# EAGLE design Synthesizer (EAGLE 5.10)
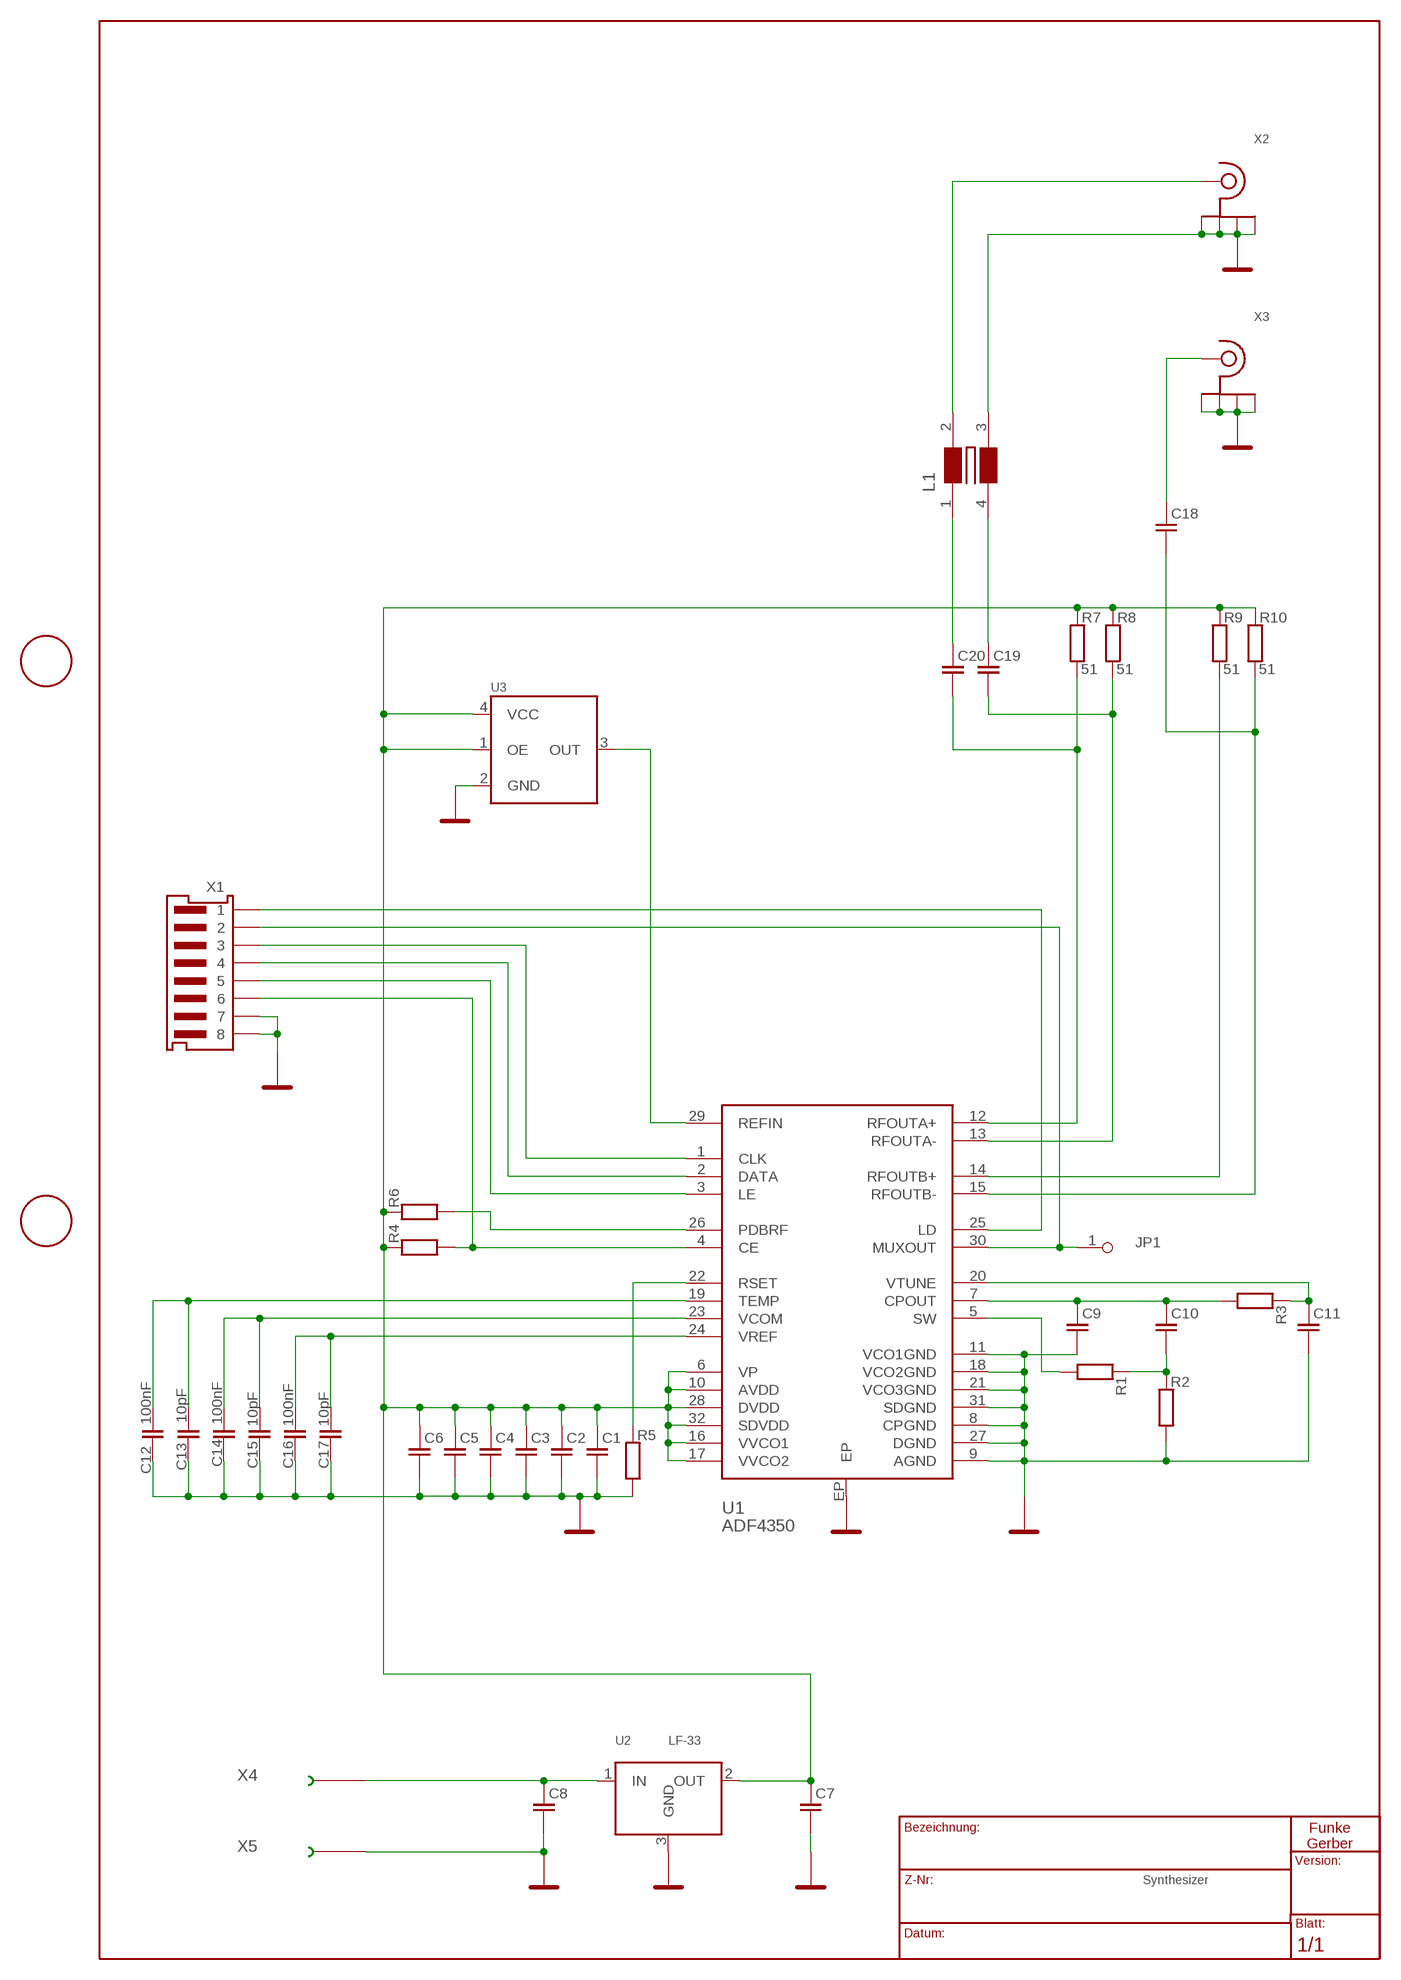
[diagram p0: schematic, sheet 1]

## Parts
C1  SMD-0603  [SOT-0603]
C2  SMD-0603  [SOT-0603]
C3  SMD-0603  [SOT-0603]
C4  SMD-0603  [SOT-0603]
C5  SMD-0603  [SOT-0603]
C6  SMD-0603  [SOT-0603]
C7  SMD-1210  [SOT-1210]
C8  SMD-1210  [SOT-1210]
C9  SMD-0603  [SOT-0603]
C10  SMD-0603  [SOT-0603]
C11  SMD-0603  [SOT-0603]
C12  100nF  SMD-0603  [SOT-0603]
C13  10pF  SMD-0603  [SOT-0603]
C14  100nF  SMD-0603  [SOT-0603]
C15  10pF  SMD-0603  [SOT-0603]
C16  100nF  SMD-0603  [SOT-0603]
C17  10pF  SMD-0603  [SOT-0603]
C18  SMD-0603  [SOT-0603]
C19  SMD-0603  [SOT-0603]
C20  SMD-0603  [SOT-0603]
JP1  PINHD-1X1  [1X01]
L1  WE-DD_M/S  [WE-DD_M/S]
R1  SMD-0603  [SMD-0603]
R2  SMD-0603  [SMD-0603]
R3  SMD-0603  [SMD-0603]
R4  SMD-0603  [SMD-0603]
R5  SMD-0603  [SMD-0603]
R6  SMD-0603  [SMD-0603]
R7  51  SMD-0603  [SMD-0603]
R8  51  SMD-0603  [SMD-0603]
R9  51  SMD-0603  [SMD-0603]
R10  51  SMD-0603  [SMD-0603]
U1  ADF4350  ADF4350CP-32-2  [CP32-2]
U2  LF-33  LF-XXX  [DPAK]
U3  SG-710  [SG710]
X1  LUMBG8  [LUMBG8]
X2  SMA-EDGE  [SMA-EDGE]
X3  SMA-EDGE  [SMA-EDGE]
X4  LÖTÖSEQ  [LÖTÖSEQ]
X5  LÖTÖSEQ  [LÖTÖSEQ]

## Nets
+3.3V: C1.2 C2.2 C3.2 C4.2 C5.2 C6.2 C7.2 R4.2 R6.2 R7.2 R8.2 R9.2 R10.2 U1.6(VP) U1.10(AVDD) U1.16(VVCO1) U1.17(VVCO2) U1.28(DVDD) U1.32(SDVDD) U2.2(OUT) U3.1(OE) U3.4(VCC)
+5V: C8.2 U2.1(IN) X4.1
A+: C20.1 R7.1 U1.12(RFOUTA+)
A-: C19.1 R8.1 U1.13(RFOUTA-)
B+: R9.1 U1.14(RFOUTB+)
B-: C18.1 R10.1 U1.15(RFOUTB-)
CH_PU: C9.2 C10.2 R3.1 U1.7(CPOUT)
GND: C1.1 C2.1 C3.1 C4.1 C5.1 C6.1 C7.1 C8.1 C9.1 C11.1 C12.2 C13.2 C14.1 C15.1 C16.1 C17.1 L1.3 R2.1 R5.1 U1.8(CPGND) U1.9(AGND) U1.11(VCO1GND) U1.18(VCO2GND) U1.21(VCO3GND) U1.27(DGND) U1.31(SDGND) U1.EP U2.3(GND) U3.2(GND) X1.7 X1.8 X2.GND@1(GND) X2.GND@2(GND) X2.GND@3(GND) X2.GND@4(GND) X3.GND@1(GND) X3.GND@2(GND) X3.GND@3(GND) X3.GND@4(GND) X5.1
N$3: C10.1 R1.2 R2.2
N$4: R1.1 U1.5(SW)
N$5: R4.1 U1.4(CE) X1.6
N$6: R5.2 U1.22(RSET)
N$7: C12.1 C13.1 U1.19(TEMP)
N$8: C14.2 C15.2 U1.23(VCOM)
N$9: C16.2 C17.2 U1.24(VREF)
N$10: U1.3(LE) X1.5
N$11: U1.2(DATA) X1.4
N$12: U1.1(CLK) X1.3
N$13: U1.25(LD) X1.1
N$14: JP1.1 U1.30(MUXOUT) X1.2
N$15: R6.1 U1.26(PDBRF)
N$16: C18.2 X3.A
N$17: U1.29(REFIN) U3.3(OUT)
N$18: C19.2 L1.4
N$19: C20.2 L1.1
N$20: L1.2 X2.A
TUNE: C11.2 R3.2 U1.20(VTUNE)

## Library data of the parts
C1-C6 C9-C20 = C_KERAM:SMD-0603
C7 C8 = C_KERAM:SMD-1210
JP1 = PINHD-Q:PINHD-1X1
L1 = WUERTH_6-6:WE-DD: SMD-Shielded Power Transformers (SEPIC) WE-DD - 1:1 transformer - Double inductor with two identical windings - Customer specific designs available upon request -- SEPIC-switching regulators -- Switching regulators with second, unregulated output voltag
R1-R10 = R:SMD-0603
U1 = ANALOG_D:ADF4350: 4.4 GHz Synthesizer mit integriertem VCO
U2 = SGS:LF-XXX
U3 = SEIK_EPS:SG-710
X1 = Z_CONNEC:LUMBG8
X2 X3 = HAMRAD:SMA-EDGE
X4 X5 = Z_CONNEC:LÖTÖSEQ

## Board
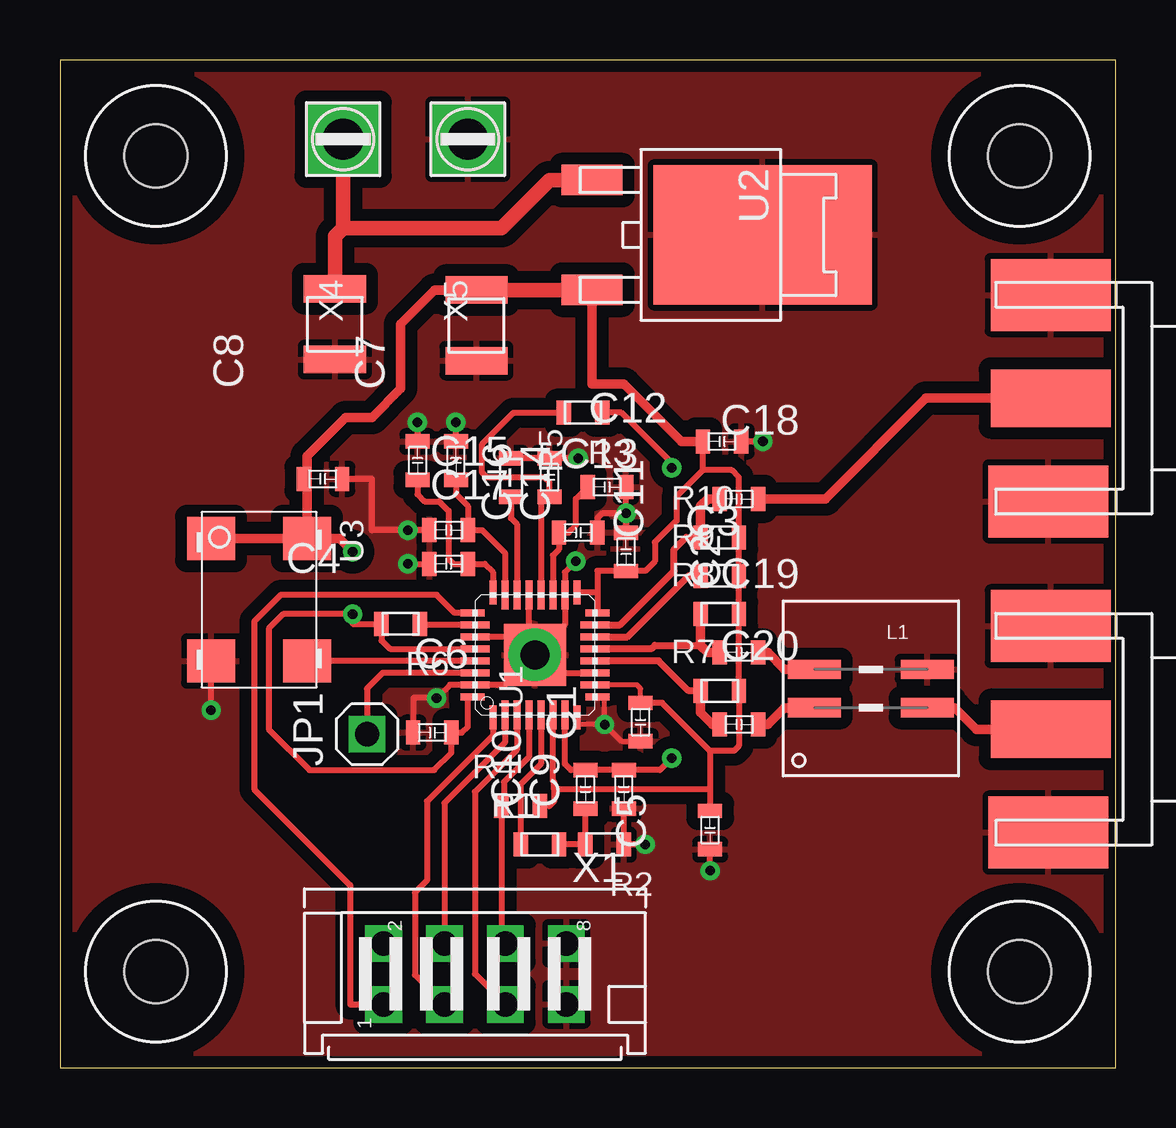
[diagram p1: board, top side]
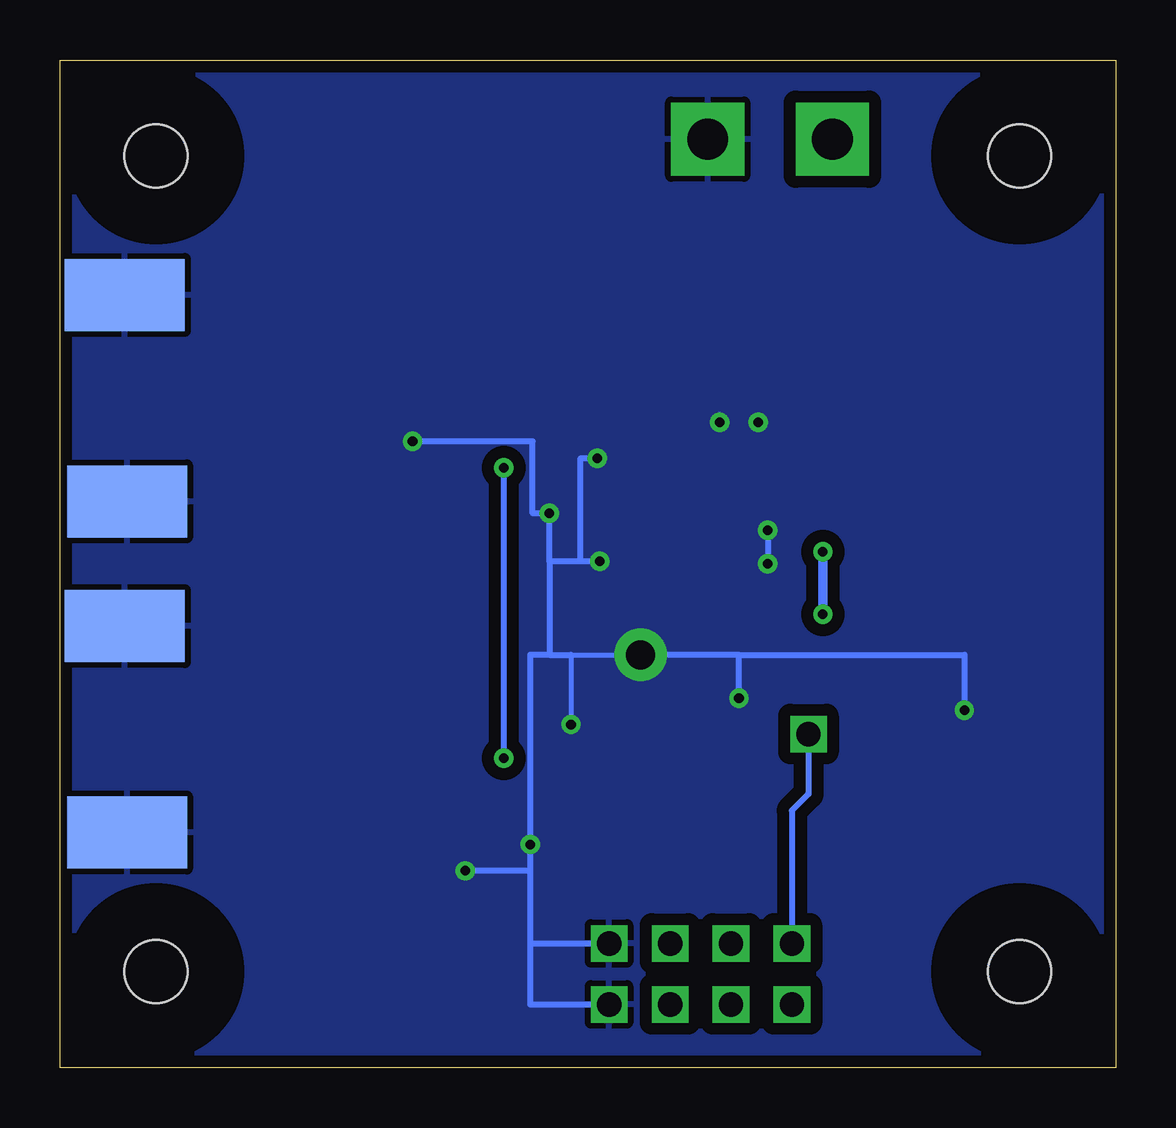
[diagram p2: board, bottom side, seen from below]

Size 44 x 42 mm. Coordinates in mm from the lower left corner, seen from the top.
Outline: 44,0 44,42 0,42 0,0 44,0
Copper layers (1*16): Top 0.035mm / dielectric 1.5mm / Bottom 0.035mm
Design rules "default": minimum track width 0.15mm, minimum drill 0.3mm, track to track 0.15mm, track to pad 0.15mm, pad to pad 0.15mm, via to via 0.15mm, smd to smd 0mil, copper to edge 0.15mm, drill to drill 0.15mm, minimum pad ring 0.15mm, minimum via ring 0.15mm, stop-mask expansion 4mil, vias tented up to drill 0mil, thermal gap 10mil

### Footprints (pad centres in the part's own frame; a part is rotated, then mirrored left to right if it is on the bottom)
SOT-0603 = smd 0.6 x 1: 1 -0.8,0; 2 0.8,0
SOT-1210 = smd 1.143 x 2.591: 1 -1.473,0; 2 1.473,0
1X01 = drill 1.016 pad 1.524 square: 1 0,0
WE-DD_M/S = smd 0.8 x 2.2: 1 0.8,-2.35; 2 0.8,2.35; 3 -0.8,2.35; 4 -0.8,-2.35
SMD-0603 = smd 0.6 x 1: 1 -0.8,0; 2 0.8,0
CP32-2 = smd 1 x 0.28: 1 -2.6,1.75; 8 -2.6,-1.75; 17 2.6,-1.75; 24 2.6,1.75 | smd 1.2 x 0.28: 2 -2.5,1.25; 3 -2.5,0.75; 4 -2.5,0.25; 5 -2.5,-0.25; 6 -2.5,-0.75; 7 -2.5,-1.25; 18 2.5,-1.25; 19 2.5,-0.75; 20 2.5,-0.25; 21 2.5,0.25; 22 2.5,0.75; 23 2.5,1.25 | smd 0.28 x 1: 9 -1.75,-2.6; 16 1.75,-2.6; 25 1.75,2.6; 32 -1.75,2.6 | smd 0.28 x 1.2: 10 -1.25,-2.5; 11 -0.75,-2.5; 12 -0.25,-2.5; 13 0.25,-2.5; 14 0.75,-2.5; 15 1.25,-2.5; 26 1.25,2.5; 27 0.75,2.5; 28 0.25,2.5; 29 -0.25,2.5; 30 -0.75,2.5; 31 -1.25,2.5 | smd 2.6 x 2.6: EP 0,0
DPAK = smd 1.27 x 2.54: 1 -2.286,-2.032; 2 2.286,-2.032 | smd 5.8 x 9.1: 3 0,5.08
SG710 = smd 1.8 x 2: 1 -2.55,-2; 2 2.55,-2; 3 2.55,2; 4 -2.55,2
DRIL-2,5 = hole 2.642: 0,0
LUMBG8 = drill 1.016 pad 1.422 square: 1 -1.27,3.81; 2 1.27,3.81; 3 -1.27,1.27; 4 1.27,1.27; 5 -1.27,-1.27; 6 1.27,-1.27; 7 -1.27,-3.81; 8 1.27,-3.81
SMA-EDGE = smd 5 x 2.4: A 0,0 | smd 5 x 3: GND@1 0,4.3; GND@2 -0.1,-4.3 | smd 5 x 3 bottom: GND@3 0,4.3; GND@4 -0.1,-4.3
LÖTÖSEQ = drill 1.702 pad 3.048 square: 1 0,0

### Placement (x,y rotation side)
C1  24.2,14.4 90 top
C2  23.6,21.5 270 top
C3  27.6,26.1 180 top
C4  10.96,24.54 180 top
C5  27.1,9.9 90 top
C6  15.52,13.96 0 top
C7  17.36,30.94 90 top
C8  11.46,30.99 90 top
C9  23.5,11.6 90 top
C10  21.9,11.6 90 top
C11  20.4,24.6 270 top
C12  22.8,24.2 0 top
C13  21.6,22.3 0 top
C14  16.5,25.3 270 top
C15  16.2,22.4 0 top
C16  14.9,25.3 270 top
C17  16.2,21 0 top
C18  28.3,23.7 0 top
C19  28.3,17.3 0 top
C20  28.3,14.3 0 top
JP1  12.8,13.9 90 top
L1  33.8,15.8 270 top
R1  20,9.3 0 top
R2  22.7,9.3 180 top
R3  21.8,27.3 180 top
R4  19.2,10.9 0 top
R5  18.8,24.6 270 top
R6  14.2,18.5 180 top
R7  27.5,15.7 0 top
R8  27.5,18.9 0 top
R9  27.5,20.5 0 top
R10  27.5,22.1 0 top
U1  19.8,17.2 90 top
U2  24.21,34.71 270 top
U3  8.3,19.5 270 top
U$11  [DRIL-2,5]  40,4 90 top
U$12  [DRIL-2,5]  40,38 90 top
U$13  [DRIL-2,5]  4,38 90 top
U$14  [DRIL-2,5]  4,4 90 top
X1  17.3,3.9 90 top
X2  41.3,14.1 0 top
X3  41.3,27.9 0 top
X4  11.8,38.7 90 top
X5  17,38.7 90 top

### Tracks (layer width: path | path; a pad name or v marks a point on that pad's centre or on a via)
+3.3V  (via drill 0.4 pad 0.8)
  Top 0.2: U1.10 24.05,15.95 24.2,15.8 C1.2
  Top 0.25: 27.1,13.2 28.1,13.2 28.3,13.4 R7.2 R8.2 R9.2 R10.2 28.3,24.6 28,24.9 26.8,24.9 | 27.1,13.2 25.1,15.2 C1.2 | 26.8,24.9 25.7,23.8 25.7,22.8 24.8,21.9 24.8,21.1 24.4,20.7 C2.2 22.4,20.7 22.4,19.8 | 22.4,19.8 U1.16 | 22.4,19.8 U1.17 | U1.6 20.55,11.95 20.6,11.9 20.6,11.6 | 27.1,13.2 27.1,11.6 | 26.8,24.9 C3.2 | U1.28 13.75,17.45 13.4,17.8 R6.2 12.2,18.5 v12.2,18.9 9.3,18.9 8.7,18.3 8.7,14.1 10.4,12.4 15.6,12.4 16.32,13.12 C6.2 16.76,13.96 17,14.2 17,15.45 U1.32 | 27.1,11.6 20.6,11.6 | 20.6,11.6 20.6,11.1 20.4,10.9 R4.2 | U2.2 21.87,32.41 | 27.1,11.6 C5.2
  Top 0.4: C3.2 25.9,26.1 23.5,28.5 22.18,28.5 U2.2 | U3.4 U3.1 | U3.4 11.65,22.05 v12.2,21.5 | 10.3,24.6 10.3,25.5 11.9,27.1 13,27.1 14.2,28.3 14.2,31 15.61,32.41 C7.2 | 10.3,24.6 U3.4 | C4.2 10.22,24.6 10.3,24.6
  Top 0.6: 21.87,32.41 C7.2
  Bottom 0.4: v12.2,21.5 v12.2,18.9
+5V
  Top 0.6: 11.8,35 18.4,35 20.4,37 U2.1 | 11.8,35 X4.1 | 11.8,35 11.46,34.66 C8.2
A+
  Top 0.3: U1.12 24.95,16.95 26.2,15.7 R7.1
  Top 0.4: C20.1 27.2,14.3 26.7,14.8 R7.1
A-
  Top 0.3: U1.13 24.65,17.45 24.8,17.6 26.7,17.6
  Top 0.4: R8.1 26.7,17.6 27,17.3 C19.1
B+
  Top 0.3: U1.14 23.65,17.95 26.2,20.5 R9.1
B-
  Top 0.3: U1.15 23.35,18.45 25.6,20.7 25.6,21.6 26.1,22.1 R10.1
  Top 0.4: R10.1 26.7,23.4 27,23.7 C18.1
CH_PU  (via drill 0.4 pad 0.8)
  Top 0.25: U1.7 21.05,12.65 21.3,12.4 C10.2 C9.2 25,12.4 v25.5,12.9 | v25.5,25 25.5,25.2 23.4,27.3 R3.1
  Bottom 0.25: v25.5,12.9 v25.5,25
GND  (via drill 0.4 pad 0.8, 1.2 pad 2.18)
  Top 0.2: C1.1 23.4,13.6 v22.7,14.3 | U1.8 21.55,14.3 v22.7,14.3 | U1.9 22.7,15.45 v22.7,14.3
  Top 0.25: v23.6,23.1 C2.1 | C13.2 22.4,22.9 22.6,23.1 v23.6,23.1 | U1.EP 21.05,18.45 U1.18 21.05,20.65 v21.5,21.1 | U1.11 20.55,16.45 U1.EP | U1.21 19.55,17.45 U1.EP | v21.6,25.4 C11.1 R5.1 | v23.6,23.1 C12.2 | U1.27 19.05,17.95 U1.EP | U1.EP 18.55,15.95 U1.31 16.25,15.95 v15.7,15.4 14.72,15.4 C6.1 | v24.4,9.3 R2.1 C9.1 | v29.3,26.1 C3.1 | v14.5,21 C17.1 | C15.1 v14.5,22.4 13,22.4 13,24.54 C4.1 | v14.9,26.9 C16.1 | C14.1 v16.5,26.9 | v6.3,14.9 U3.2 | v27.1,8.2 C5.1
  Bottom 0.2: v22.7,14.3 22.7,17.2 U1.EP
  Bottom 0.25: 23.6,21.1 23.6,17.2 | 23.6,21.1 v23.6,23.1 24.3,23.1 24.3,26.1 v29.3,26.1 | 23.6,17.2 22.7,17.2 | 22.3,21.1 23.6,21.1 | v21.5,21.1 22.3,21.1 | v21.6,25.4 22.3,25.4 22.3,21.1 | v15.7,15.4 15.7,17.2 | 15.7,17.2 19.7,17.2 | 23.6,17.2 24.4,17.2 v24.4,9.3 24.4,8.2 | 14.2,21 v14.5,21 v14.5,22.4 14.3,22.4 | 14.9,27.1 v14.9,26.9 | v16.5,26.9 16.5,27.2 | 24.4,5.17 X1.8 | 24.4,8.2 24.4,5.17 | X1.7 24.4,2.63 24.4,5.17 | v6.3,14.9 6.3,17.2 15.7,17.2 | 24.4,8.2 v27.1,8.2
  other vias: 19.8,17.2
  pour Bottom (isolate 0.5): 0.4,41.8 0.4,0.3 43.4,0.3 43.4,41.8
  pour Top (isolate 0.5): 0.4,41.8 0.4,0.3 43.4,0.3 43.4,41.8
N$3
  Top 0.25: R1.2 R2.2 C10.1
N$4
  Top 0.25: U1.5 20.05,12.65 19.2,11.8 R1.1
N$5
  Top 0.25: U1.4 19.55,12.95 18.5,11.9 18.5,11 R4.1 18.4,5.34 X1.6
N$6
  Top 0.25: U1.22 19.05,22.65 18.8,22.9 R5.2
N$7
  Top 0.25: U1.19 20.55,21.35 20.8,21.6 C13.1 21.2,22.3 21.5,22.6 21.5,23.7 C12.1
N$8
  Top 0.25: U1.23 18.55,21.45 17.6,22.4 C15.2 17,23.4 16.5,23.9 C14.2
N$9
  Top 0.25: U1.24 18.05,20.65 17.7,21 C17.2 16.4,21 16.2,21.2 16.2,23.2 15.8,23.6 15.2,23.6 14.9,23.9 C16.2
N$10
  Top 0.25: U1.3 19.05,13.25 17.3,11.5 17.3,3.9 X1.5
N$11
  Top 0.25: U1.2 18.55,13.55 16.03,11.03 X1.4
N$12
  Top 0.25: U1.1 18.05,13.85 15.3,11.1 15.3,7.8 14.8,7.3 14.8,3.86 X1.3
N$13
  Top 0.25: U1.25 16.45,18.95 15.7,19.7 9.2,19.7 8.1,18.6 8.1,11.6 12.1,7.6 12.1,2.63 X1.1
N$14
  Top 0.25: U1.30 13.45,16.45 12.8,15.8 JP1.1
  Bottom 0.25: X1.2 13.49,10.71 12.8,11.4 JP1.1
N$15
  Top 0.25: U1.26 15.05,18.45 R6.1
N$16
  Top 0.4: C18.2 31.9,23.7 36.1,27.9 X3.A
N$17
  Top 0.25: U1.29 U3.3
N$18
  Top 0.4: C19.2 29.5,17.3 30.2,16.6 L1.4
N$19
  Top 0.4: C20.2 29.5,14.3 30.2,15 L1.1
N$20
  Top 0.4: L1.2 37.3,15 38.2,14.1 X2.A
TUNE
  Top 0.25: U1.20 20.05,23.75 C11.2 20.4,24.4 20.2,24.6 17.8,24.6 17.6,24.8 17.6,26 18.9,27.3 R3.2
